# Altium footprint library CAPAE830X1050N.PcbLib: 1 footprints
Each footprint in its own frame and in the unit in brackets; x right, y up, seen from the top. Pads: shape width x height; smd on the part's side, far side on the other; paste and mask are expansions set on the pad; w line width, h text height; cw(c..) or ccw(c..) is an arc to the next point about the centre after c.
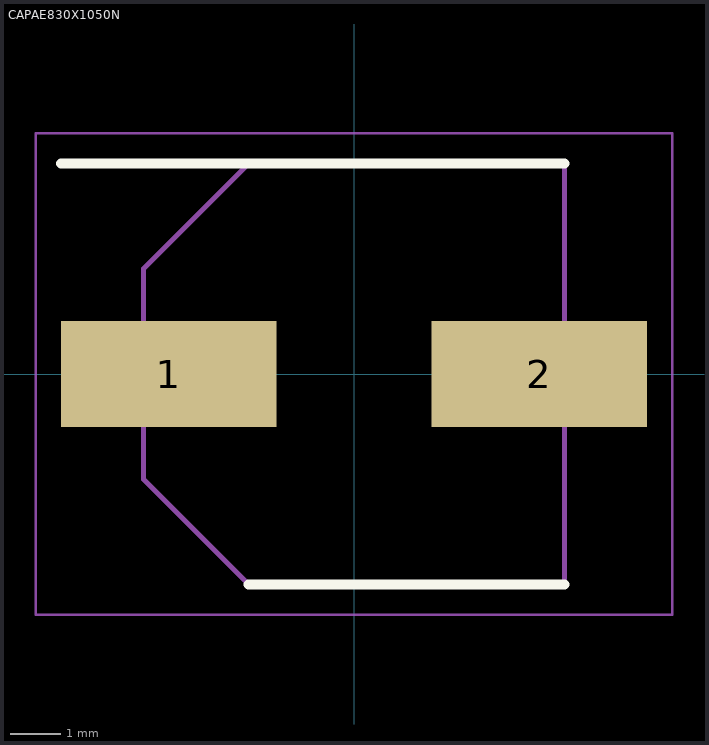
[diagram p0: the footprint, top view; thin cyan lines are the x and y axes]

## CAPAE830X1050N [mm]
pads (2):
  rect 4.25x2.1 smd: 1(-3.65,0) 2(3.65,0)
Top Overlay:
  lines w0.2: -5.775,4.15 4.15,4.15 ; -2.075,-4.15 4.15,-4.15
Mechanical 15:
  lines w0.1: -4.15,-2.075 -4.15,2.075 -2.075,4.15 4.15,4.15 4.15,-4.15 -2.075,-4.15 -4.15,-2.075
Mechanical 20:
  lines w0.05: -6.275,-4.75 6.275,-4.75 6.275,4.75 -6.275,4.75 -6.275,-4.75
